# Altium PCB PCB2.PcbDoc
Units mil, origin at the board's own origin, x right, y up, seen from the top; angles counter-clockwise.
Board outline 1968 x 1968 mil, 4 copper layers (Top Layer, Internal Plane 1, Internal Plane 2, Bottom Layer), stack 18.2 mil thick; 11 components, 11 nets, 36 pads, 0 vias.
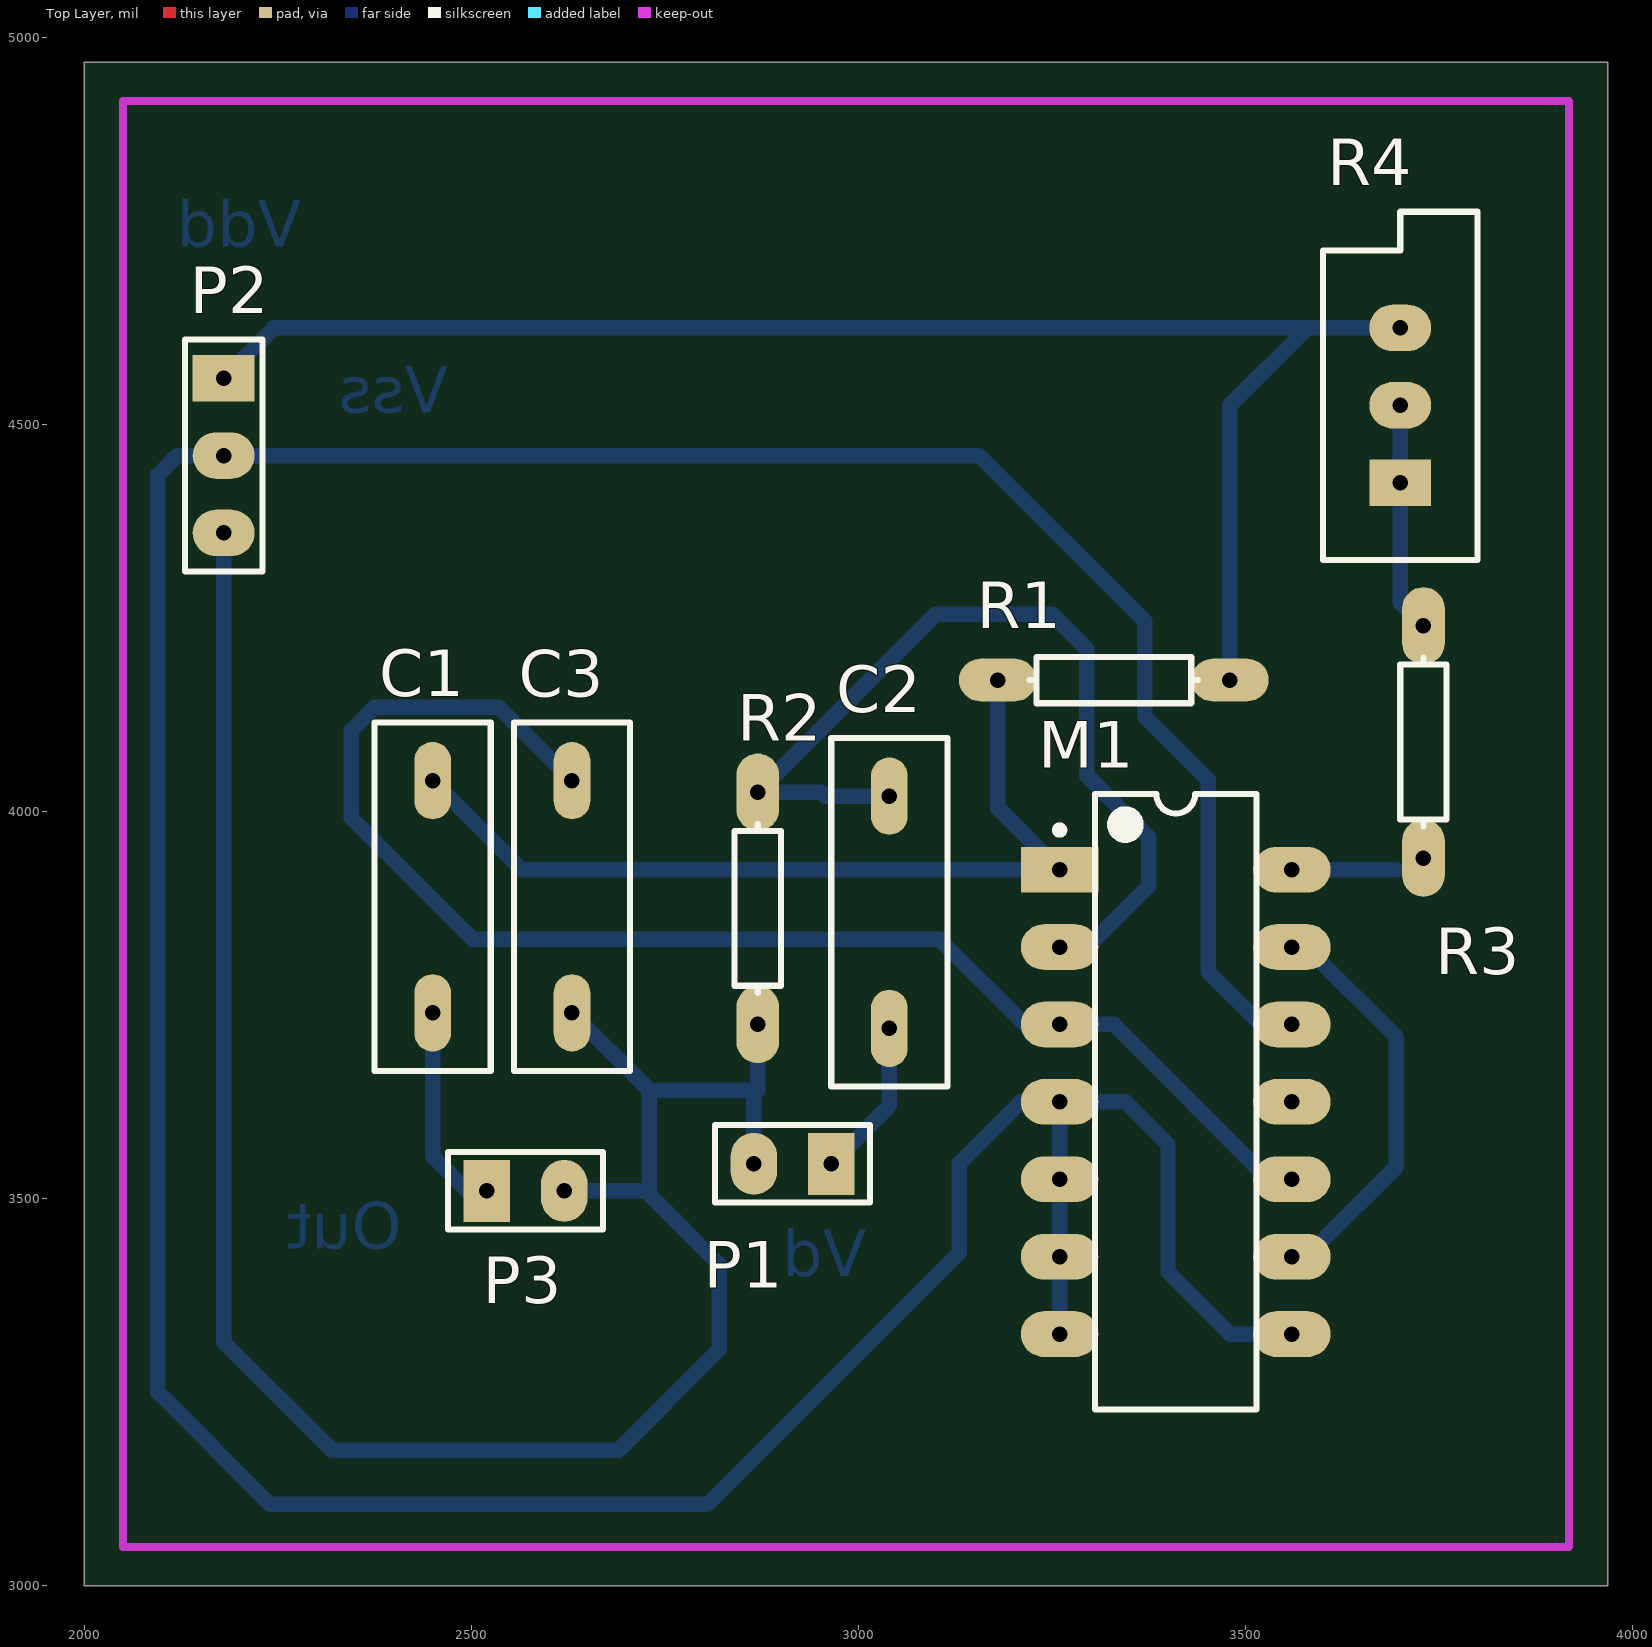
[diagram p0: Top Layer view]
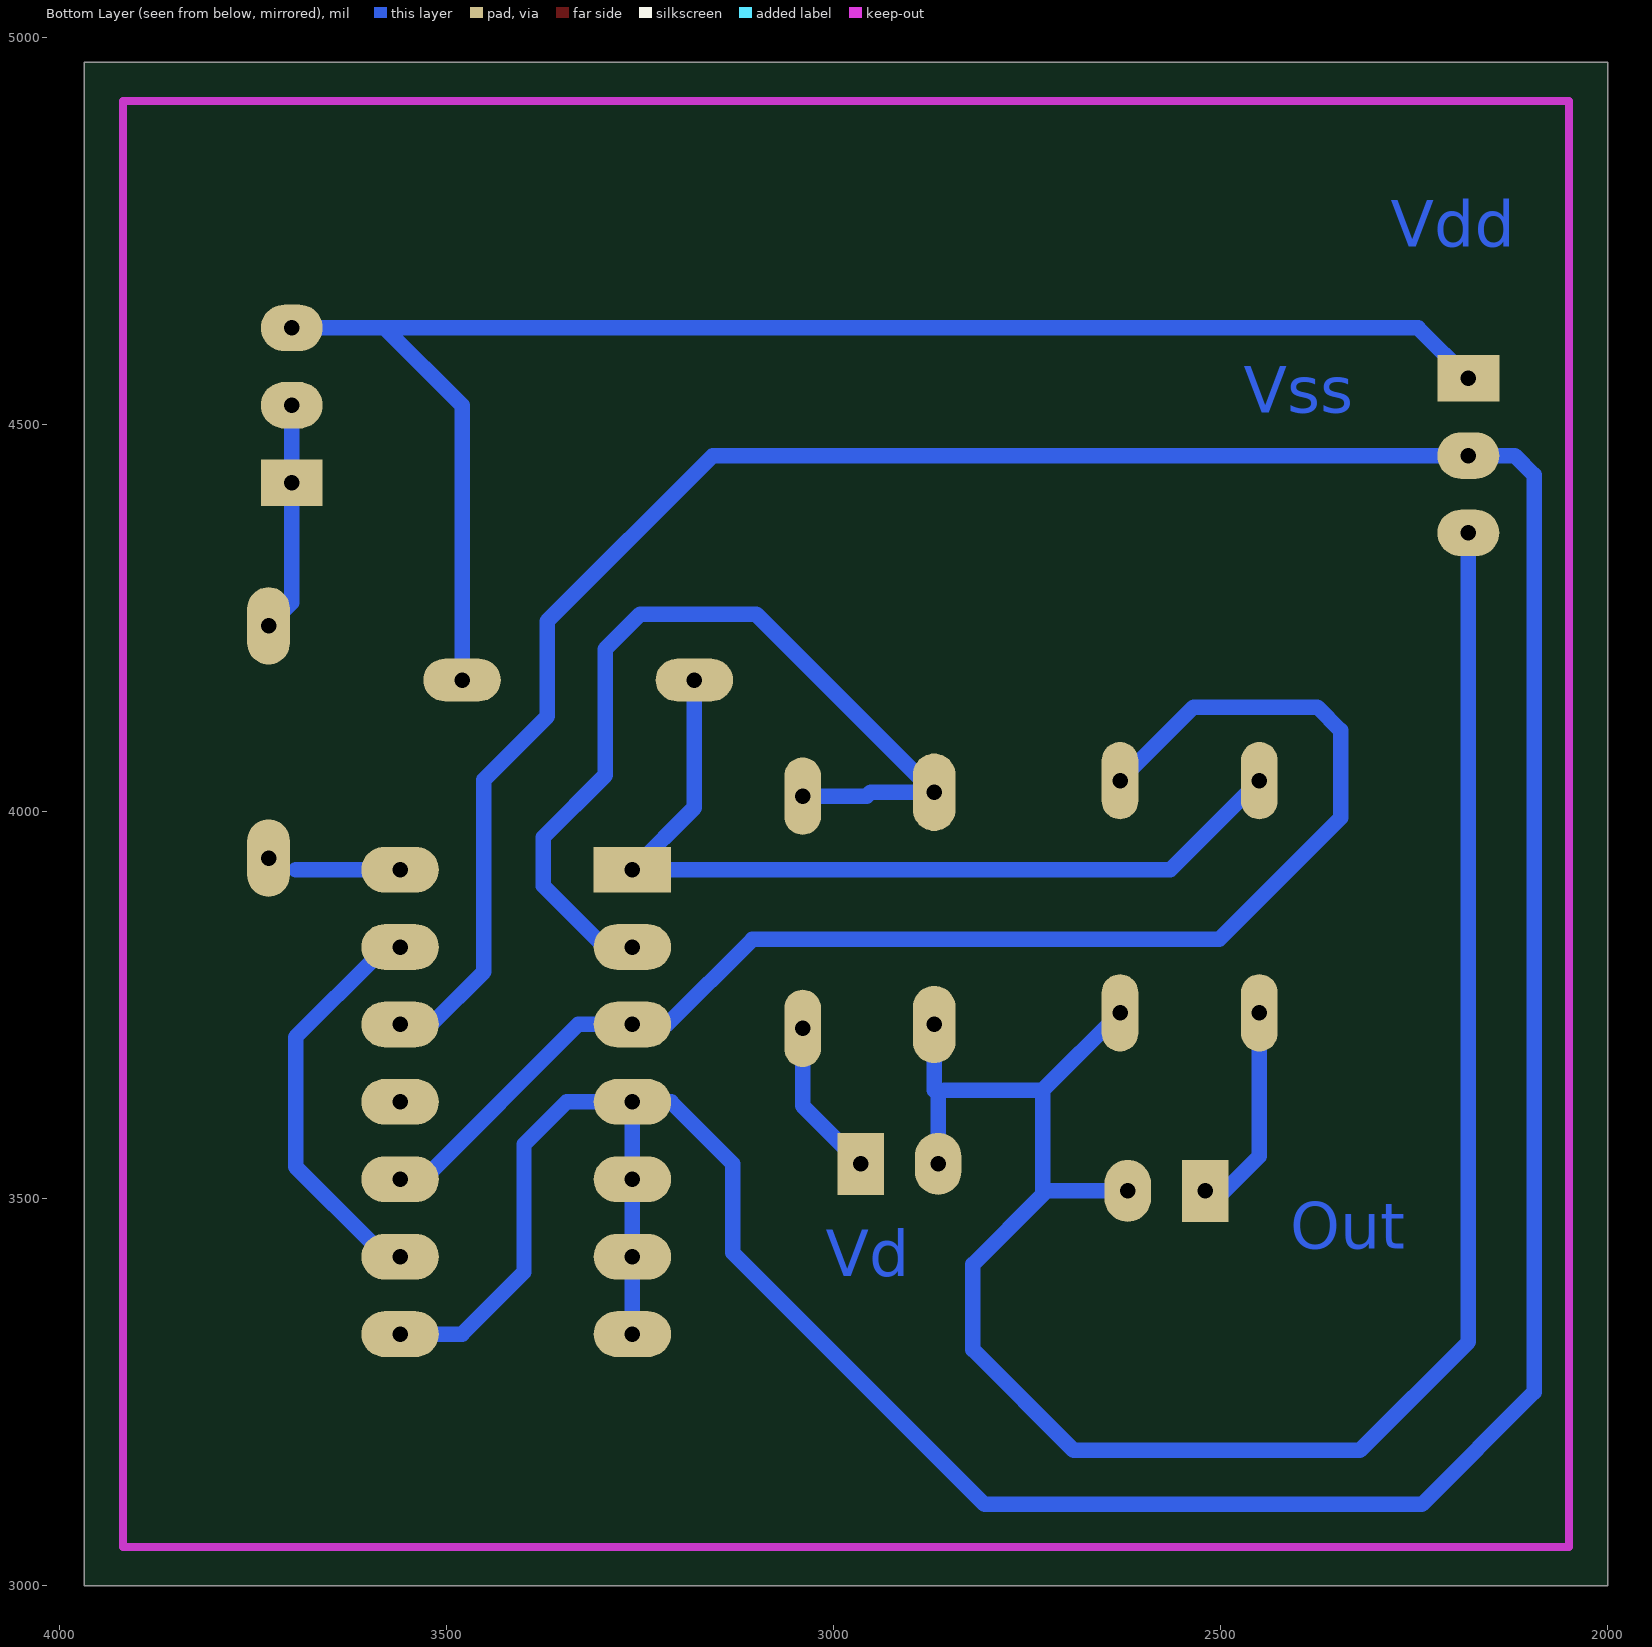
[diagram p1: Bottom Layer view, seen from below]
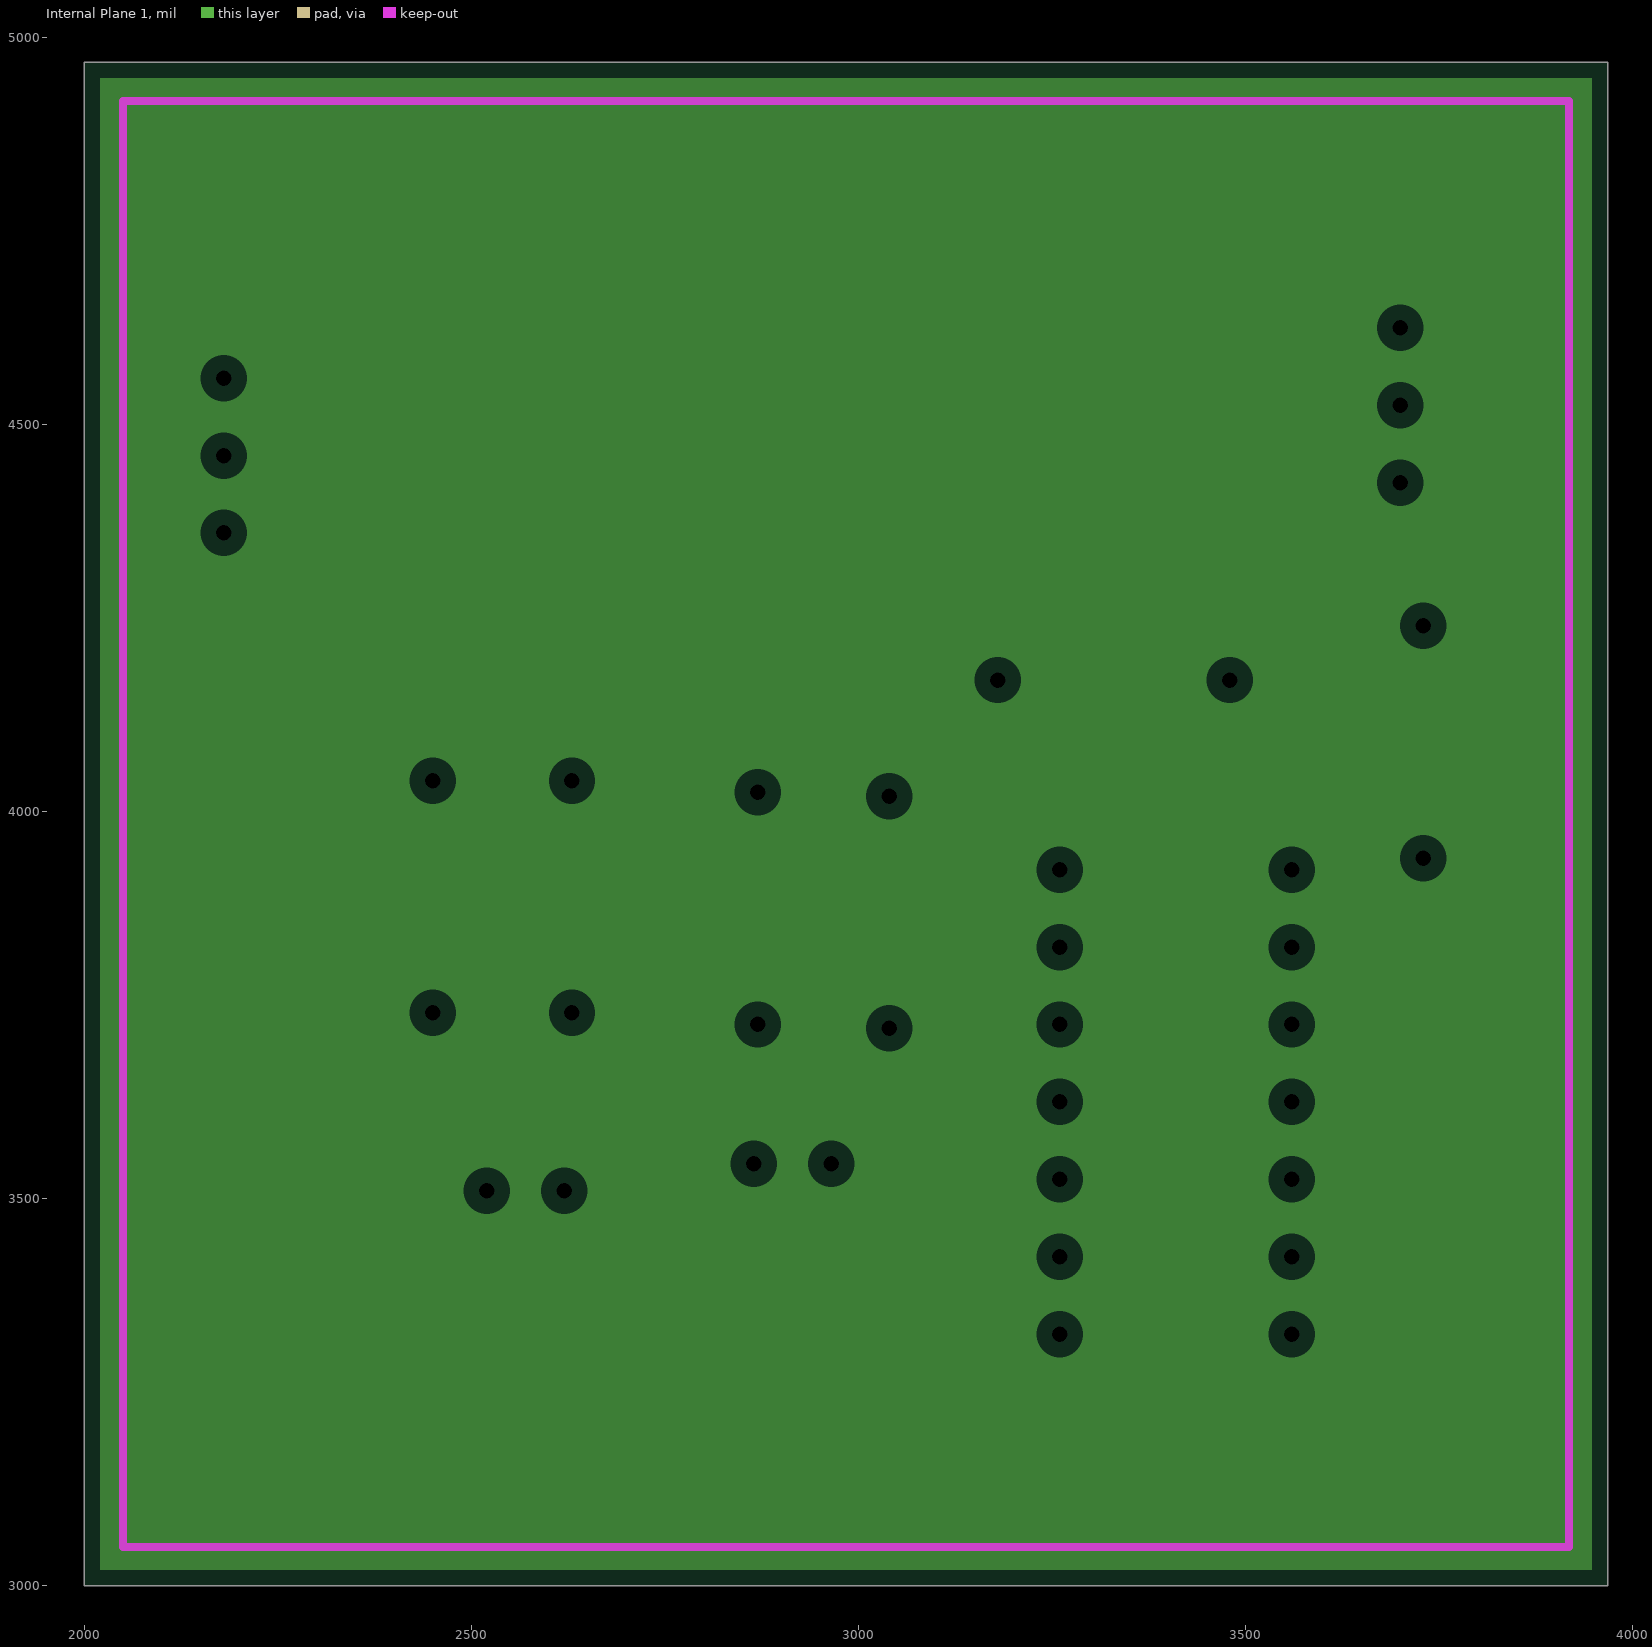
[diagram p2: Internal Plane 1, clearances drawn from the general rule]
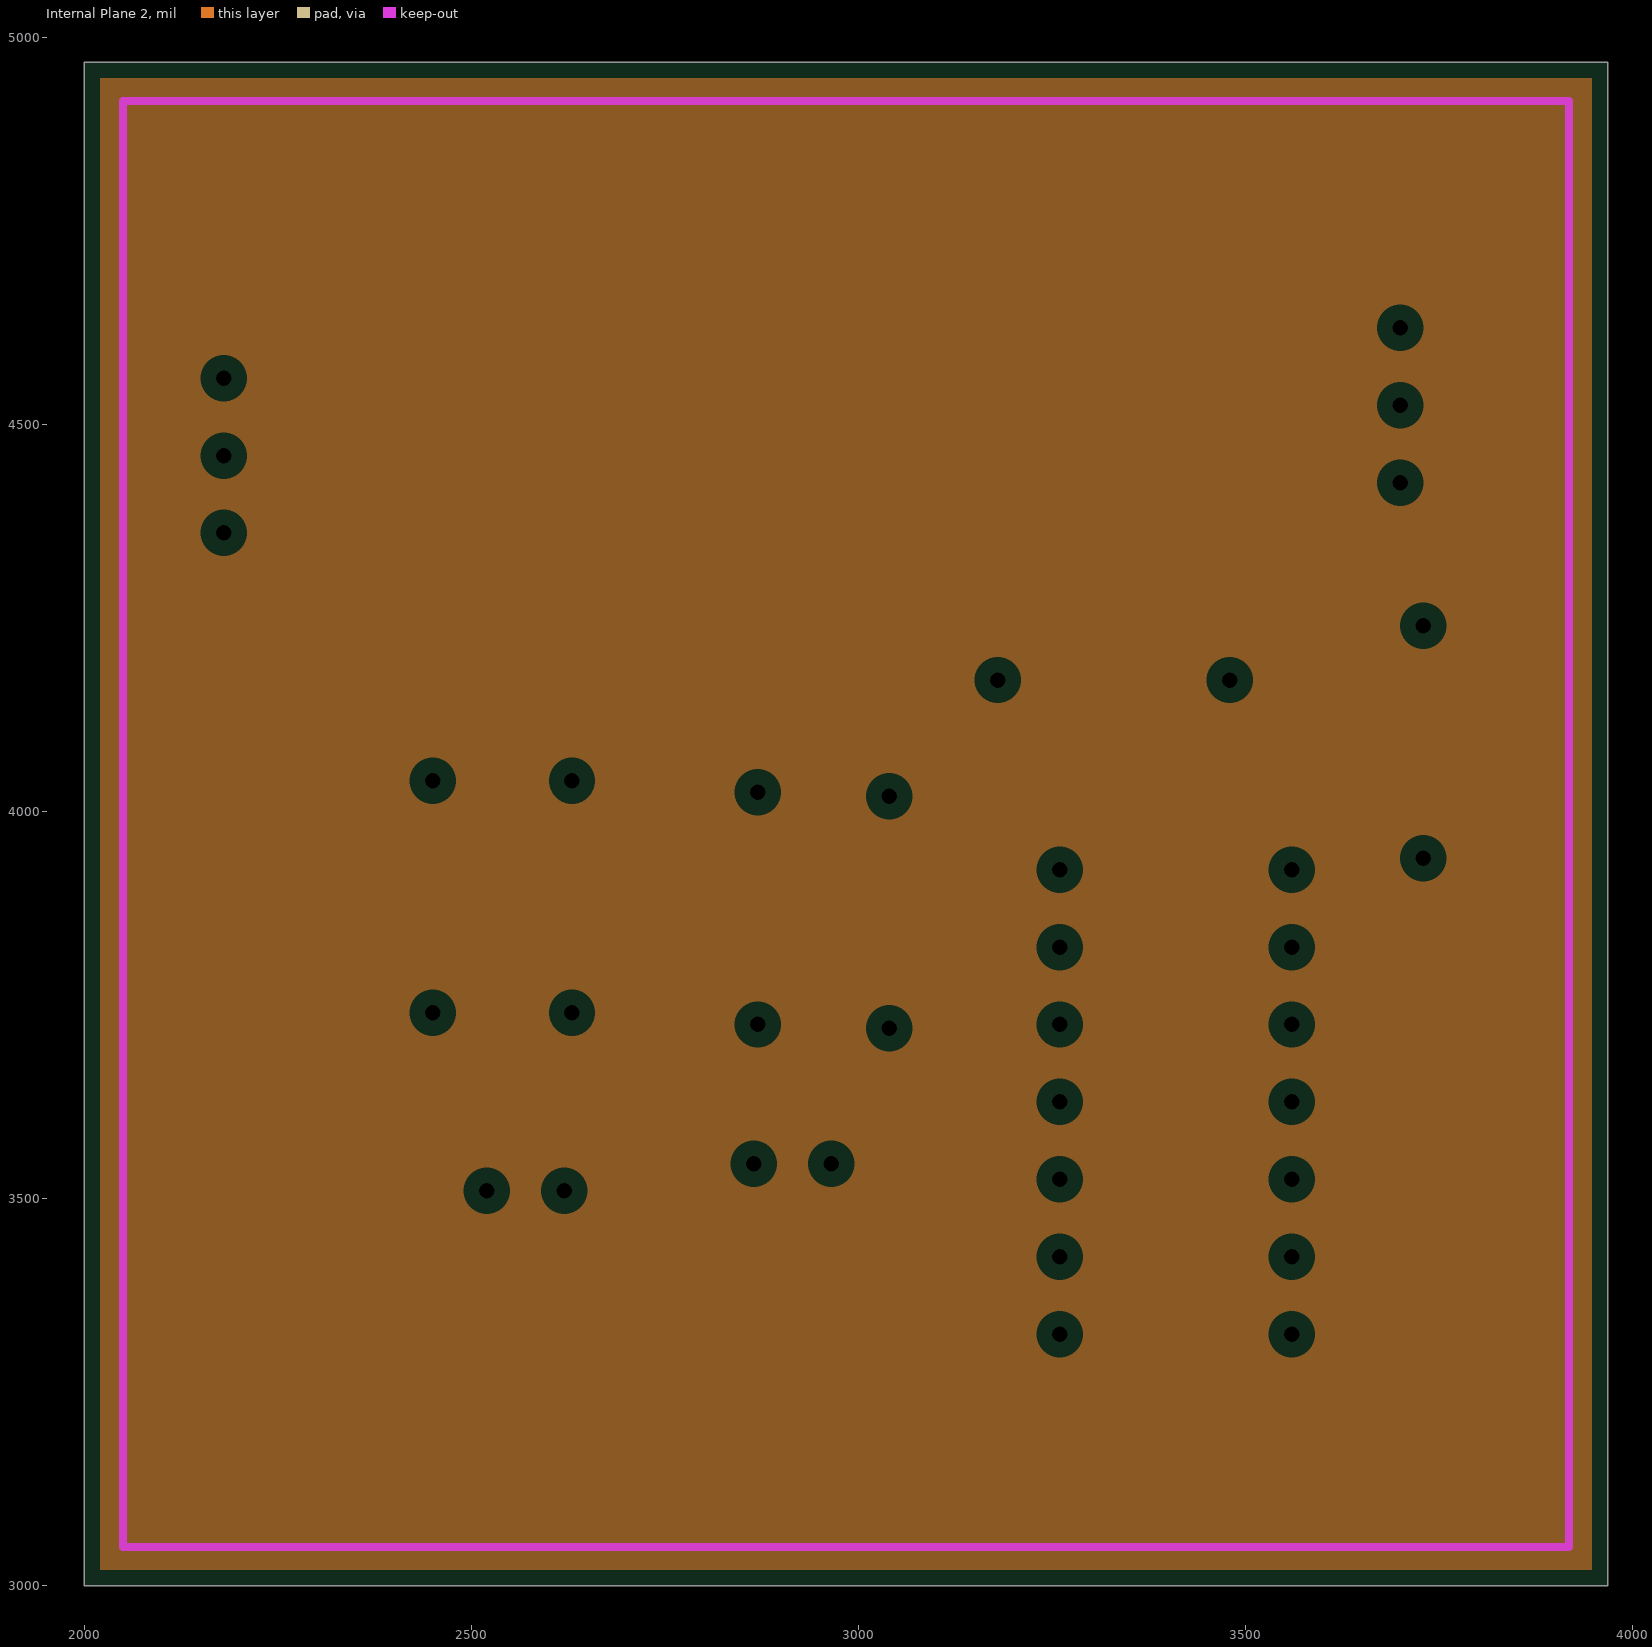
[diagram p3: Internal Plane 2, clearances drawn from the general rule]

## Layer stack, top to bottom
Top Solder: solder mask 0.4, Solder Resist, Dk 3.5
Top Layer: signal copper 1.4
Internal Plane 1: plane copper 1.4
Internal Plane 2: plane copper 1.4
Dielectric 1: dielectric 12.6, FR-4, Dk 4.8
Bottom Layer: signal copper 1.4
Bottom Solder: solder mask 0.4, Solder Resist, Dk 3.5

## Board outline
2000,3000 3968,3000 3968,4968 2000,4968

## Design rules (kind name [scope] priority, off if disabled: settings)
Clearance [All] p1: gap=30
PlaneClearance [All] p1: clearance=20
PlaneConnect [All] p1: planeconnectstyle=Relief reliefexpansion=20 reliefentries=4 reliefconductorwidth=10 reliefairgap=10
PolygonConnect [All] p1: connectstyle=Relief reliefconductorwidth=10 reliefentries=4 polygonreliefangle="90 Angle" airgapwidth=10
RoutingVias [All] p1: holewidth=32 width=62 viastyle="Through Hole" minholewidth=28 minwidth=50 maxholewidth=28 maxwidth=50
SolderMaskExpansion [All] p1: expansion=4
Width [All] p1: maxlimit=20 minlimit=20 preferedwidth=20
28 further rules are at their usual default settings.

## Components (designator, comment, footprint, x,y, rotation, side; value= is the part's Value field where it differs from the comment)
C1 "C3" RAD-0.3 2450,3890 r270 top
C2 "C2" RAD-0.3 3040,3870 r90 top
C3 "C1" RAD-0.3 2630,3890 r90 top
M1 "ALD1106" DIP-14 3410,3625 r0 top
P1 "Header 2" HDR1X2 2965,3545 r180 top
P2 "Header 3" HDR1X3 2180,4560 r270 top
P3 "Header 2" HDR1X2 2520,3510 r0 top
R1 "RD" AXIAL-0.3 3330,4170 r0 top
R2 "Res1" AXIAL-0.3 2870,3875 r90 top
R3 "Res1" AXIAL-0.3 3730,4090 r90 top
R4 "RPot" VR5 3700,4525 r90 top

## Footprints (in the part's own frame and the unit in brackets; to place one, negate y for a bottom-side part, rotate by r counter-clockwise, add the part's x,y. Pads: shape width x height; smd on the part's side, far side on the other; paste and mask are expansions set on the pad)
AXIAL-0.3 [mil] "Axial Device, Thru-Hole; 2 Leads; 0.3 in Pin Spacing"
  oval 100x55.12 hole 20: 1(-150,0) 2(150,0)
  silkscreen extent -109,-30 109,30
DIP-14 [mil] "DIP, 14-Pin, Row Spacing 7.62 mm, Pitch 2.54 mm"
  rect 100x59.06 hole 20: 1(-150,300)
  oval 100x59.06 hole 20: 2(-150,200) 3(-150,100) 4(-150,0) 5(-150,-100) 6(-150,-200) 7(-150,-300) 8(150,-300) 9(150,-200) 10(150,-100) 11(150,0) 12(150,100) 13(150,200) 14(150,300)
  silkscreen extent -155,-398 104,398, body extent -142,-398 142,398, height 200
HDR1X2 [mil] "Connector; Header; 2 Position"
  rect 60x80 hole 20: 1(0,0)
  oval 60x80 hole 20: 2(100,0)
  silkscreen extent -50,-50 150,50
HDR1X3 [mil] "Connector; Header; 3 Position"
  rect 60x80 hole 20: 1(0,0)
  oval 60x80 hole 20: 2(100,0) 3(200,0)
  silkscreen extent -50,-50 250,50
RAD-0.3 [mil] "Radial Cap, Thru-Hole; 2 Leads; 0.3 in Pin Spacing"
  oval 100x47.24 hole 20: 1(-150,0) 2(150,0)
  silkscreen extent -225,-75 225,75
VR5 [mil] "Thru-Hole; 3 Leads"
  rect 60x80 hole 20: 1(-100,0)
  oval 60x80 hole 20: 2(0,0) 3(100,0)
  silkscreen extent -200,-100 250,100

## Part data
C1 C2 C3: library part Cap, "Capacitor"
M1: "Quad N-channel matched MOSFET array"
P1 P3: "Header, 2-Pin"
P2: "Header, 3-Pin"
R1: library part Res1, "Resistor"
R2 R3: "Resistor"
R4: "Potentiometer"

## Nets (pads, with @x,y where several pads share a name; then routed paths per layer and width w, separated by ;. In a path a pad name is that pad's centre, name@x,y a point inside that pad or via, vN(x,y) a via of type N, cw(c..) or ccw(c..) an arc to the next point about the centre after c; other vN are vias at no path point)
GND: C3.1 P1.2 P2.3 P3.2 R2.1 | length 2714.5
  Bottom Layer w20: P2.3 2180,3315 2320,3175 2690,3175 2820,3305 2820,3415 2730,3505 2730,3640 ; P3.2 2725,3510 ; C3.1 2730,3640 ; 2857,3640 2730,3640 ; P1.2 2865,3632 ; 2870,3640 R2.1
NetC1_1: C1.1 M1.1 R1.1 | length 1135.8
  Bottom Layer w20: C1.1 2565,3925 M1.1 3180,4005 R1.1
NetC1_2: C1.2 P3.1 | length 252.2
  Bottom Layer w20: C1.2 2450,3555 P3.1@2497.5,3507.5
NetC2_1: C2.1 P1.1 | length 206.1
  Bottom Layer w20: P1.1 3040,3620 C2.1
NetC2_2: C2.2 M1.2 R2.2 | length 1197.9
  Bottom Layer w20: C2.2 2957,4020 2952,4025 R2.2 3100,4255 3250,4255 3295,4210 3295,4047 3375,3967 3375,3903.9 3296.1,3825 M1.2
NetC3_2: C3.2 M1.3 M1.10 | length 1858.2
  Bottom Layer w20: C3.2 2535,4135 2375,4135 2345,4105 2345,3992 2502,3835 3105,3835 3215,3725 M1.3 3330,3725 3530,3525 M1.10
NetM1_4: M1.4 M1.5 M1.6 M1.7 M1.8 M1.12 P2.2 | length 5510.9
  Bottom Layer w20: M1.7 M1.6 M1.5 M1.4 ; M1.8 3480,3325 3400,3405 3400,3570 3345,3625 M1.4 ; M1.12 3520,3725 3452,3793 3452,4041 3370,4123 3370,4246.01 3156.01,4460 P2.2 2120,4460 2095,4435 2095,3250 2240,3105 2805,3105 3130,3430 3130,3545 3210,3625 M1.4
NetM1_9: M1.9 M1.13 | length 533.9
  Bottom Layer w20: M1.9 3575,3440 3593.8,3440 3695,3541.2 3695,3708.8 3588.8,3815 3570,3815 M1.13
NetM1_14: M1.14 R3.1 | length 135
  Bottom Layer w20: M1.14 3695,3925
NetP2_1: P2.1 R1.2 R4.3 | length 2163.3
  Bottom Layer w20: P2.1 2245,4625 R4.3 3580,4625 3480,4525 R1.2
NetR3_2: R3.2 R4.1 R4.2 | length 297.4
  Bottom Layer w20: R4.2 R4.1 3700,4270 R3.2
pads on no net: M1.11

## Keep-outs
Keep-Out Layer:
  lines w10: 2050,3050 3918,3050 3918,4918 2050,4918 2050,3050

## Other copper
Bottom Layer:
  text "Vdd" at 2280,4730 h60
  text "Vss" at 2470,4515 h60
  text "Out" at 2410,3435 h60
  text "Vd" at 3010,3400 h60

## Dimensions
2050,3050 to 3918,3050 on Mechanical 1
2050,3050 to 2050,4918 on Mechanical 1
